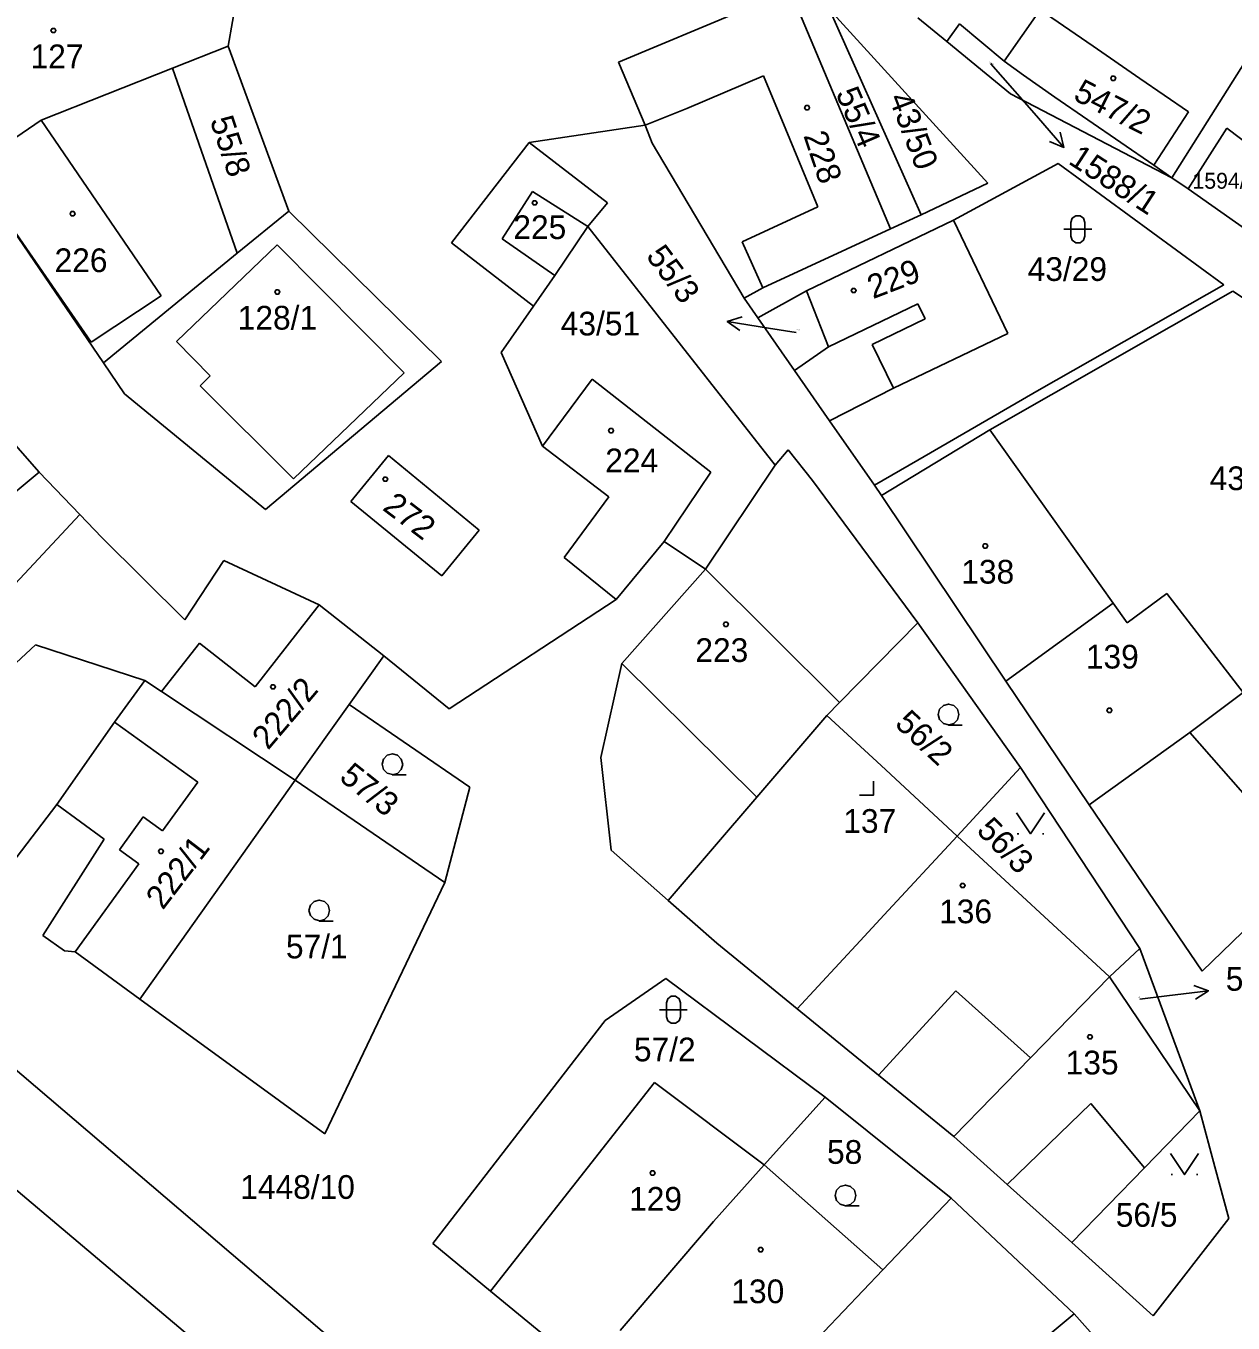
# Model space of a CAD drawing. Extents: x -580630 to -576196, y -1189024 to -1183567.
# Drawn here: x -578833.2 to -578746.6, y -1185615.1 to -1185522.1 of the extents above; entities that cross this region are included whole.
import ezdxf

# ---------------------------------------------------------------- set-up
doc = ezdxf.new("R2010")
doc.units = 0
for name, color, linetype in [('Vrstva 1', 7, 'Continuous'), ('Vrstva 16', 7, 'Continuous'), ('Vrstva 18', 7, 'Continuous'), ('Vrstva 19', 7, 'Continuous'), ('Vrstva 25', 7, 'Continuous'), ('Vrstva 4', 7, 'Continuous')]:
    doc.layers.add(name, color=color, linetype=linetype)

msp = doc.modelspace()

# ---------------------------------------------------------------- linework, layer by layer
at = {"layer": 'Vrstva 1'}
for p, q in [((-578731.57, -1185502.07), (-578751.03, -1185532.96)), ((-578818.69, -1185523.52), (-578817.05, -1185514.17)), ((-578778.1, -1185520.19), (-578771.19, -1185536.6)), ((-578790.69, -1185524.65), (-578781.89, -1185520.97)), ((-578775.57, -1185520.89), (-578769, -1185535.61)), ((-578764.22, -1185533.34), (-578775.57, -1185520.89)), ((-578767.17, -1185523.17), (-578769.25, -1185521.47)), ((-578760.47, -1185520.91), (-578763.06, -1185524.59)), ((-578760.47, -1185520.91), (-578756.67, -1185523.51)), ((-578766.25, -1185521.92), (-578767.17, -1185523.17)), ((-578766.25, -1185521.92), (-578763.06, -1185524.59)), ((-578762.6, -1185526.92), (-578767.17, -1185523.17)), ((-578822.67, -1185525.09), (-578818.69, -1185523.52)), ((-578814.34, -1185535.34), (-578818.69, -1185523.52)), ((-578756.67, -1185523.51), (-578753.33, -1185525.82)), ((-578832.1, -1185528.82), (-578822.67, -1185525.09)), ((-578822.67, -1185525.09), (-578818.03, -1185538.36)), ((-578788.8, -1185529.18), (-578790.69, -1185524.65)), ((-578763.06, -1185524.59), (-578761.66, -1185525.59)), ((-578761.66, -1185525.59), (-578759.42, -1185527.17)), ((-578753.33, -1185525.82), (-578749.83, -1185528.21)), ((-578751.03, -1185532.96), (-578762.6, -1185526.92)), ((-578759.42, -1185527.17), (-578752.33, -1185532.03)), ((-578832.1, -1185528.82), (-578837.14, -1185532.25)), ((-578749.83, -1185528.21), (-578752.33, -1185532.03)), ((-578788.8, -1185529.18), (-578797.11, -1185530.41)), ((-578788.28, -1185530.46), (-578788.8, -1185529.18)), ((-578749.86, -1185533.74), (-578747.08, -1185529.4)), ((-578747.08, -1185529.4), (-578745.22, -1185530.79)), ((-578797.11, -1185530.41), (-578802.68, -1185537.62)), ((-578791.49, -1185534.75), (-578797.11, -1185530.41)), ((-578781.69, -1185541.57), (-578788.28, -1185530.46)), ((-578827.62, -1185546.22), (-578837.14, -1185532.25)), ((-578766.69, -1185535.98), (-578759.18, -1185531.92)), ((-578747.29, -1185540.62), (-578759.18, -1185531.92)), ((-578752.33, -1185532.03), (-578751.03, -1185532.96)), ((-578769, -1185535.61), (-578764.22, -1185533.34)), ((-578751.03, -1185532.96), (-578749.86, -1185533.74)), ((-578745.82, -1185536.58), (-578749.86, -1185533.74)), ((-578818.03, -1185538.36), (-578814.34, -1185535.34)), ((-578814.34, -1185535.34), (-578803.4, -1185546.12)), ((-578792.9, -1185536.45), (-578791.49, -1185534.75)), ((-578795.26, -1185539.96), (-578792.9, -1185536.45)), ((-578779.46, -1185553.54), (-578792.9, -1185536.45)), ((-578777.23, -1185541.06), (-578766.69, -1185535.98)), ((-578769, -1185535.61), (-578771.19, -1185536.6)), ((-578766.69, -1185535.98), (-578762.79, -1185544.1)), ((-578771.19, -1185536.6), (-578780.36, -1185540.83)), ((-578827.62, -1185546.22), (-578818.03, -1185538.36)), ((-578802.68, -1185537.62), (-578796.8, -1185542.16)), ((-578796.8, -1185542.16), (-578795.26, -1185539.96)), ((-578780.36, -1185540.83), (-578781.69, -1185541.57)), ((-578780.7, -1185542.98), (-578777.23, -1185541.06)), ((-578777.23, -1185541.06), (-578775.64, -1185545.06)), ((-578764.07, -1185551.02), (-578746.66, -1185541.08)), ((-578760.55, -1185548.16), (-578747.29, -1185540.62)), ((-578746.66, -1185541.08), (-578728.09, -1185553.41)), ((-578781.69, -1185541.57), (-578780.7, -1185542.98)), ((-578799.11, -1185545.48), (-578796.8, -1185542.16)), ((-578778.07, -1185546.77), (-578780.7, -1185542.98)), ((-578841.52, -1185543.51), (-578832.24, -1185554.04)), ((-578762.79, -1185544.1), (-578770.99, -1185548.04)), ((-578796.16, -1185552.19), (-578799.11, -1185545.48)), ((-578775.64, -1185545.06), (-578778.07, -1185546.77)), ((-578826.11, -1185548.44), (-578827.62, -1185546.22)), ((-578803.4, -1185546.12), (-578816, -1185556.73)), ((-578792.58, -1185547.38), (-578796.16, -1185552.19)), ((-578792.58, -1185547.38), (-578784.08, -1185554.05)), ((-578778.07, -1185546.77), (-578775.57, -1185550.36)), ((-578816, -1185556.73), (-578826.11, -1185548.44)), ((-578770.99, -1185548.04), (-578775.57, -1185550.36)), ((-578769.25, -1185553.18), (-578760.55, -1185548.16)), ((-578772.34, -1185554.99), (-578775.57, -1185550.36)), ((-578764.07, -1185551.02), (-578771.85, -1185555.72)), ((-578755.23, -1185563.44), (-578764.07, -1185551.02)), ((-578796.16, -1185552.19), (-578791.39, -1185555.83)), ((-578807.2, -1185552.86), (-578809.89, -1185556.16)), ((-578800.68, -1185558.21), (-578807.2, -1185552.86)), ((-578778.53, -1185552.44), (-578779.46, -1185553.54)), ((-578776.79, -1185554.66), (-578778.53, -1185552.44)), ((-578772.34, -1185554.99), (-578769.25, -1185553.18)), ((-578832.24, -1185554.04), (-578855.96, -1185573.95)), ((-578832.24, -1185554.04), (-578829.33, -1185557.09)), ((-578786.58, -1185557.78), (-578784.08, -1185554.05)), ((-578784.47, -1185561.01), (-578779.46, -1185553.54)), ((-578769.23, -1185564.85), (-578776.79, -1185554.66)), ((-578772.34, -1185554.99), (-578771.85, -1185555.72)), ((-578791.39, -1185555.83), (-578794.59, -1185560.17)), ((-578771.85, -1185555.72), (-578762.92, -1185569.03)), ((-578809.89, -1185556.16), (-578803.36, -1185561.49)), ((-578850.68, -1185579.93), (-578829.33, -1185557.09)), ((-578829.33, -1185557.09), (-578827.73, -1185558.74)), ((-578787.42, -1185559.03), (-578786.58, -1185557.78)), ((-578827.73, -1185558.74), (-578821.8, -1185564.64)), ((-578803.36, -1185561.49), (-578800.68, -1185558.21)), ((-578790.86, -1185563.19), (-578787.42, -1185559.03)), ((-578787.42, -1185559.03), (-578784.47, -1185561.01)), ((-578821.8, -1185564.64), (-578818.99, -1185560.38)), ((-578812.16, -1185563.57), (-578818.99, -1185560.38)), ((-578794.59, -1185560.17), (-578790.86, -1185563.19)), ((-578790.45, -1185567.77), (-578784.47, -1185561.01)), ((-578790.86, -1185563.19), (-578802.84, -1185571.01)), ((-578762.92, -1185569.03), (-578755.23, -1185563.44)), ((-578754.22, -1185564.85), (-578755.23, -1185563.44)), ((-578751.39, -1185562.75), (-578754.22, -1185564.85)), ((-578745.91, -1185569.85), (-578751.39, -1185562.75)), ((-578807.52, -1185567.22), (-578812.16, -1185563.57)), ((-578774.86, -1185570.57), (-578769.23, -1185564.85)), ((-578769.23, -1185564.85), (-578761.89, -1185575.22)), ((-578849.08, -1185581.71), (-578832.49, -1185566.44)), ((-578832.49, -1185566.44), (-578824.66, -1185568.98)), ((-578807.52, -1185567.22), (-578810.02, -1185570.72)), ((-578802.84, -1185571.01), (-578807.52, -1185567.22)), ((-578791.96, -1185574.52), (-578790.45, -1185567.77)), ((-578824.66, -1185568.98), (-578826.83, -1185571.98)), ((-578824.66, -1185568.98), (-578823.46, -1185569.78)), ((-578762.92, -1185569.03), (-578756.96, -1185577.9)), ((-578823.46, -1185569.78), (-578813.89, -1185576.14)), ((-578749.73, -1185572.71), (-578745.91, -1185569.85)), ((-578810.02, -1185570.72), (-578813.89, -1185576.14)), ((-578810.02, -1185570.72), (-578801.35, -1185576.64)), ((-578775.77, -1185571.5), (-578774.86, -1185570.57)), ((-578775.77, -1185571.5), (-578780.78, -1185577.34)), ((-578771.88, -1185575.09), (-578775.77, -1185571.5)), ((-578826.83, -1185571.98), (-578830.97, -1185577.88)), ((-578749.73, -1185572.71), (-578756.96, -1185577.9)), ((-578791.22, -1185581.15), (-578791.96, -1185574.52)), ((-578766.42, -1185580.14), (-578771.88, -1185575.09)), ((-578766.42, -1185580.14), (-578761.89, -1185575.22)), ((-578753.33, -1185588.21), (-578761.89, -1185575.22)), ((-578813.89, -1185576.14), (-578825.02, -1185591.83)), ((-578813.89, -1185576.14), (-578803.15, -1185583.47)), ((-578803.15, -1185583.47), (-578801.35, -1185576.64)), ((-578780.78, -1185577.34), (-578787.15, -1185584.75)), ((-578830.97, -1185577.88), (-578840.93, -1185590.91)), ((-578827.57, -1185580.37), (-578830.97, -1185577.88)), ((-578756.96, -1185577.9), (-578748.86, -1185589.83)), ((-578771.65, -1185585.79), (-578766.42, -1185580.14)), ((-578755.49, -1185590.23), (-578766.42, -1185580.14)), ((-578831.96, -1185587.27), (-578827.57, -1185580.37)), ((-578787.15, -1185584.75), (-578791.22, -1185581.15)), ((-578740.35, -1185581.57), (-578748.86, -1185589.83)), ((-578811.76, -1185601.48), (-578803.15, -1185583.47)), ((-578783.66, -1185587.83), (-578787.15, -1185584.75)), ((-578773.38, -1185587.66), (-578771.65, -1185585.79)), ((-578830.41, -1185588.36), (-578831.96, -1185587.27)), ((-578777.9, -1185592.53), (-578773.38, -1185587.66)), ((-578829.66, -1185588.44), (-578830.41, -1185588.36)), ((-578825.02, -1185591.83), (-578829.66, -1185588.44)), ((-578779.74, -1185591.03), (-578783.66, -1185587.83)), ((-578755.49, -1185590.23), (-578753.33, -1185588.21)), ((-578749.02, -1185599.84), (-578753.33, -1185588.21)), ((-578787.3, -1185590.36), (-578791.66, -1185593.37)), ((-578775.89, -1185598.87), (-578787.3, -1185590.36)), ((-578761.17, -1185596.05), (-578755.49, -1185590.23)), ((-578749.02, -1185599.84), (-578755.49, -1185590.23)), ((-578764.45, -1185656.14), (-578840.93, -1185590.91)), ((-578777.9, -1185592.53), (-578779.74, -1185591.03)), ((-578825.02, -1185591.83), (-578811.76, -1185601.48)), ((-578772.07, -1185597.28), (-578777.9, -1185592.53)), ((-578791.66, -1185593.37), (-578804.02, -1185609.36)), ((-578766.66, -1185601.69), (-578761.17, -1185596.05)), ((-578788.12, -1185597.8), (-578799.88, -1185612.76)), ((-578780.25, -1185603.72), (-578788.12, -1185597.8)), ((-578766.66, -1185601.69), (-578772.07, -1185597.28)), ((-578842.76, -1185598.03), (-578767.43, -1185661.53)), ((-578780.25, -1185603.72), (-578775.89, -1185598.87)), ((-578766.85, -1185606.09), (-578775.89, -1185598.87)), ((-578749.02, -1185599.84), (-578752.98, -1185603.92)), ((-578747.94, -1185603.85), (-578749.02, -1185599.84)), ((-578766.66, -1185601.69), (-578762.83, -1185605.12)), ((-578783.88, -1185607.77), (-578780.25, -1185603.72)), ((-578780.25, -1185603.72), (-578771.76, -1185611.24)), ((-578752.98, -1185603.92), (-578758.19, -1185609.29)), ((-578746.94, -1185607.55), (-578747.94, -1185603.85)), ((-578762.83, -1185605.12), (-578758.19, -1185609.29)), ((-578771.76, -1185611.24), (-578766.85, -1185606.09)), ((-578758.03, -1185614.39), (-578766.85, -1185606.09)), ((-578783.88, -1185607.77), (-578790.59, -1185615.58)), ((-578752.36, -1185614.53), (-578746.94, -1185607.55)), ((-578804.02, -1185609.36), (-578799.88, -1185612.76)), ((-578758.19, -1185609.29), (-578752.36, -1185614.53)), ((-578780.45, -1185620.36), (-578771.76, -1185611.24)), ((-578799.88, -1185612.76), (-578793.01, -1185618.4)), ((-578762.65, -1185618.22), (-578758.03, -1185614.39)), ((-578758.03, -1185614.39), (-578755.17, -1185617.6))]:
    msp.add_line(p, q, dxfattribs=at)
at = {"layer": 'Vrstva 16'}
for p, q in [((-578764.01, -1185524.78), (-578760.74, -1185528.51)), ((-578758.763, -1185530.767), (-578760.74, -1185528.51)), ((-578782.901, -1185543.24), (-578779.94, -1185543.72)), ((-578777.97, -1185544.04), (-578779.94, -1185543.72)), ((-578748.402, -1185591.229), (-578751.38, -1185591.59)), ((-578753.33, -1185591.83), (-578751.38, -1185591.59))]:
    msp.add_line(p, q, dxfattribs=at)
for points in [[(-578759.046, -1185529.685), (-578758.763, -1185530.767), (-578759.798, -1185530.344)], [(-578781.994, -1185543.893), (-578782.901, -1185543.24), (-578781.834, -1185542.906)], [(-578749.455, -1185590.853), (-578748.402, -1185591.229), (-578749.334, -1185591.846)]]:
    msp.add_lwpolyline(points, dxfattribs=at)
at = {"layer": 'Vrstva 25'}
for p, q in [((-578762.11, -1185579.98), (-578762.01, -1185579.98)), ((-578760.31, -1185579.98), (-578760.21, -1185579.98)), ((-578751.07, -1185604.41), (-578750.97, -1185604.41)), ((-578749.27, -1185604.41), (-578749.17, -1185604.41))]:
    msp.add_line(p, q, dxfattribs=at)
for points in [[(-578831.12, -1185522.24), (-578831.03, -1185522.39), (-578831.12, -1185522.54), (-578831.3, -1185522.54), (-578831.39, -1185522.39), (-578831.3, -1185522.24)], [(-578755.14, -1185525.66), (-578755.05, -1185525.81), (-578755.14, -1185525.96), (-578755.32, -1185525.96), (-578755.41, -1185525.81), (-578755.32, -1185525.66)], [(-578777.09, -1185527.77), (-578777, -1185527.92), (-578777.09, -1185528.07), (-578777.27, -1185528.07), (-578777.36, -1185527.92), (-578777.27, -1185527.77)], [(-578796.62, -1185534.59), (-578796.53, -1185534.74), (-578796.62, -1185534.89), (-578796.8, -1185534.89), (-578796.89, -1185534.74), (-578796.8, -1185534.59)], [(-578829.75, -1185535.37), (-578829.66, -1185535.52), (-578829.75, -1185535.67), (-578829.93, -1185535.67), (-578830.02, -1185535.52), (-578829.93, -1185535.37)], [(-578758.27, -1185536.14), (-578758.17, -1185535.85), (-578757.92, -1185535.67), (-578757.61, -1185535.67), (-578757.36, -1185535.85), (-578757.26, -1185536.14), (-578757.26, -1185537.14), (-578757.36, -1185537.43), (-578757.61, -1185537.61), (-578757.92, -1185537.61), (-578758.17, -1185537.43), (-578758.27, -1185537.14)], [(-578815.07, -1185540.98), (-578814.98, -1185541.13), (-578815.07, -1185541.28), (-578815.25, -1185541.28), (-578815.34, -1185541.13), (-578815.25, -1185540.98)], [(-578773.75, -1185540.88), (-578773.66, -1185541.03), (-578773.75, -1185541.18), (-578773.93, -1185541.18), (-578774.02, -1185541.03), (-578773.93, -1185540.88)], [(-578791.14, -1185550.92), (-578791.05, -1185551.07), (-578791.14, -1185551.22), (-578791.32, -1185551.22), (-578791.41, -1185551.07), (-578791.32, -1185550.92)], [(-578807.33, -1185554.4), (-578807.24, -1185554.55), (-578807.33, -1185554.7), (-578807.51, -1185554.7), (-578807.6, -1185554.55), (-578807.51, -1185554.4)], [(-578764.32, -1185559.19), (-578764.23, -1185559.34), (-578764.32, -1185559.49), (-578764.5, -1185559.49), (-578764.59, -1185559.34), (-578764.5, -1185559.19)], [(-578782.91, -1185564.81), (-578782.82, -1185564.96), (-578782.91, -1185565.11), (-578783.09, -1185565.11), (-578783.18, -1185564.96), (-578783.09, -1185564.81)], [(-578815.38, -1185569.29), (-578815.29, -1185569.44), (-578815.38, -1185569.59), (-578815.56, -1185569.59), (-578815.65, -1185569.44), (-578815.56, -1185569.29)], [(-578755.41, -1185570.98), (-578755.32, -1185571.13), (-578755.41, -1185571.28), (-578755.59, -1185571.28), (-578755.68, -1185571.13), (-578755.59, -1185570.98)], [(-578823.41, -1185581.08), (-578823.32, -1185581.23), (-578823.41, -1185581.38), (-578823.59, -1185581.38), (-578823.68, -1185581.23), (-578823.59, -1185581.08)], [(-578765.93, -1185583.54), (-578765.84, -1185583.69), (-578765.93, -1185583.84), (-578766.11, -1185583.84), (-578766.2, -1185583.69), (-578766.11, -1185583.54)], [(-578787.27, -1185592.09), (-578787.17, -1185591.8), (-578786.92, -1185591.62), (-578786.61, -1185591.62), (-578786.36, -1185591.8), (-578786.26, -1185592.09), (-578786.26, -1185593.09), (-578786.36, -1185593.38), (-578786.61, -1185593.56), (-578786.92, -1185593.56), (-578787.17, -1185593.38), (-578787.27, -1185593.09)], [(-578756.81, -1185594.38), (-578756.72, -1185594.53), (-578756.81, -1185594.68), (-578756.99, -1185594.68), (-578757.08, -1185594.53), (-578756.99, -1185594.38)], [(-578788.17, -1185604.15), (-578788.08, -1185604.3), (-578788.17, -1185604.45), (-578788.35, -1185604.45), (-578788.44, -1185604.3), (-578788.35, -1185604.15)], [(-578780.42, -1185609.64), (-578780.33, -1185609.79), (-578780.42, -1185609.94), (-578780.6, -1185609.94), (-578780.69, -1185609.79), (-578780.6, -1185609.64)]]:
    msp.add_lwpolyline(points, close=True, dxfattribs=at)
for points in [[(-578758.77, -1185536.64), (-578757.5, -1185536.64), (-578756.77, -1185536.64)], [(-578767.03, -1185572.16), (-578767.41, -1185572.06), (-578767.68, -1185571.79), (-578767.78, -1185571.42), (-578767.68, -1185571.05), (-578767.41, -1185570.78), (-578767.04, -1185570.68), (-578766.67, -1185570.78), (-578766.4, -1185571.05), (-578766.3, -1185571.43), (-578766.4, -1185571.81), (-578766.67, -1185572.08), (-578767.05, -1185572.18), (-578766.05, -1185572.18)], [(-578806.9, -1185575.73), (-578807.28, -1185575.63), (-578807.55, -1185575.36), (-578807.65, -1185574.99), (-578807.55, -1185574.62), (-578807.28, -1185574.35), (-578806.91, -1185574.25), (-578806.54, -1185574.35), (-578806.27, -1185574.62), (-578806.17, -1185575), (-578806.27, -1185575.38), (-578806.54, -1185575.65), (-578806.92, -1185575.75), (-578805.92, -1185575.75)], [(-578773.43, -1185577.21), (-578772.43, -1185577.21), (-578772.43, -1185576.21)], [(-578762.16, -1185578.48), (-578761.16, -1185579.98), (-578760.16, -1185578.48)], [(-578812.14, -1185586.21), (-578812.52, -1185586.11), (-578812.79, -1185585.84), (-578812.89, -1185585.47), (-578812.79, -1185585.1), (-578812.52, -1185584.83), (-578812.15, -1185584.73), (-578811.78, -1185584.83), (-578811.51, -1185585.1), (-578811.41, -1185585.48), (-578811.51, -1185585.86), (-578811.78, -1185586.13), (-578812.16, -1185586.23), (-578811.16, -1185586.23)], [(-578787.77, -1185592.59), (-578786.5, -1185592.59), (-578785.77, -1185592.59)], [(-578751.12, -1185602.91), (-578750.12, -1185604.41), (-578749.12, -1185602.91)], [(-578774.42, -1185606.64), (-578774.8, -1185606.54), (-578775.07, -1185606.27), (-578775.17, -1185605.9), (-578775.07, -1185605.53), (-578774.8, -1185605.26), (-578774.43, -1185605.16), (-578774.06, -1185605.26), (-578773.79, -1185605.53), (-578773.69, -1185605.91), (-578773.79, -1185606.29), (-578774.06, -1185606.56), (-578774.44, -1185606.66), (-578773.44, -1185606.66)]]:
    msp.add_lwpolyline(points, dxfattribs=at)
at = {"layer": 'Vrstva 4'}
for p, q in [((-578785.81, -1185527.99), (-578780.3, -1185525.63)), ((-578780.3, -1185525.63), (-578778.71, -1185529.48)), ((-578788.8, -1185529.18), (-578785.81, -1185527.99)), ((-578823.49, -1185541.42), (-578832.1, -1185528.82)), ((-578778.71, -1185529.48), (-578776.41, -1185535.04)), ((-578828.5, -1185544.73), (-578837.14, -1185532.25)), ((-578799.04, -1185537.33), (-578796.86, -1185533.94)), ((-578796.86, -1185533.94), (-578792.9, -1185536.45)), ((-578776.41, -1185535.04), (-578781.84, -1185537.53)), ((-578795.26, -1185539.96), (-578799.04, -1185537.33)), ((-578815.18, -1185537.76), (-578822.39, -1185544.68)), ((-578806.07, -1185546.92), (-578815.18, -1185537.76)), ((-578781.84, -1185537.53), (-578780.36, -1185540.83)), ((-578828.5, -1185544.73), (-578823.49, -1185541.42)), ((-578769.24, -1185541.98), (-578775.64, -1185545.06)), ((-578768.72, -1185543.07), (-578769.24, -1185541.98)), ((-578772.51, -1185544.89), (-578768.72, -1185543.07)), ((-578822.39, -1185544.68), (-578819.98, -1185547.15)), ((-578770.99, -1185548.04), (-578772.51, -1185544.89)), ((-578819.98, -1185547.15), (-578820.7, -1185547.85)), ((-578814, -1185554.54), (-578806.07, -1185546.92)), ((-578820.7, -1185547.85), (-578814, -1185554.54)), ((-578784.47, -1185561.01), (-578774.86, -1185570.57)), ((-578812.16, -1185563.57), (-578816.76, -1185569.43)), ((-578820.73, -1185566.31), (-578823.46, -1185569.78)), ((-578816.76, -1185569.43), (-578820.73, -1185566.31)), ((-578790.45, -1185567.77), (-578780.78, -1185577.34)), ((-578820.87, -1185576.28), (-578826.83, -1185571.98)), ((-578744.55, -1185578.61), (-578749.73, -1185572.71)), ((-578823.39, -1185579.77), (-578820.87, -1185576.28)), ((-578826.47, -1185581.12), (-578824.77, -1185578.77)), ((-578824.77, -1185578.77), (-578823.39, -1185579.77)), ((-578825.09, -1185582.12), (-578826.47, -1185581.12)), ((-578829.66, -1185588.44), (-578825.09, -1185582.12)), ((-578772.07, -1185597.28), (-578766.51, -1185591.24)), ((-578766.51, -1185591.24), (-578761.17, -1185596.05)), ((-578762.83, -1185605.12), (-578756.83, -1185599.32)), ((-578756.83, -1185599.32), (-578752.98, -1185603.92))]:
    msp.add_line(p, q, dxfattribs=at)

# ---------------------------------------------------------------- texts
at = {"layer": 'Vrstva 16'}
for s, rotation, p in [('1588/1', 326.98701, (-578758.527, -1185531.889)), ('55/3', 306.93349, (-578788.778, -1185538.574))]:
    msp.add_text(s, height=1.7, rotation=rotation, dxfattribs=at).set_placement(p)
msp.add_text('56/4', height=1.7, dxfattribs=at).set_placement((-578747.163, -1185591.23))
at = {"layer": 'Vrstva 18'}
for s, height, rotation, p in [('1588/1', 0.1, 323.77845, (-578764.177, -1185524.657)), ('55/4', 1.7, 293.29709, (-578775.152, -1185526.884)), ('43/50', 1.7, 291.00526, (-578771.348, -1185527.215)), ('55/8', 1.7, 288.31236, (-578820.008, -1185528.827)), ('56/2', 1.7, 316.96025, (-578770.964, -1185572.185)), ('57/3', 1.7, 321.42932, (-578810.799, -1185576.071)), ('56/3', 1.7, 314.43924, (-578765.105, -1185579.815)), ('56/4', 0.1, 313.5798, (-578753.443, -1185591.711))]:
    msp.add_text(s, height=height, rotation=rotation, dxfattribs=at).set_placement(p)
for s, height, p in [('1594/12', 1.14, (-578749.551, -1185533.73)), ('43/29', 1.7, (-578761.364, -1185540.34)), ('43/51', 1.7, (-578794.839, -1185544.25)), ('55/3', 0.1, (-578777.942, -1185543.94)), ('43/28', 1.7, (-578748.314, -1185555.34)), ('57/1', 1.7, (-578814.543, -1185588.91)), ('57/2', 1.7, (-578789.594, -1185596.29)), ('58', 1.7, (-578775.752, -1185603.64)), ('1448/10', 1.7, (-578817.819, -1185606.15)), ('56/5', 1.7, (-578755.048, -1185608.15))]:
    msp.add_text(s, height=height, dxfattribs=at).set_placement(p)
at = {"layer": 'Vrstva 19'}
for s, p in [('127', (-578832.85, -1185525.09)), ('225', (-578798.238, -1185537.34)), ('226', (-578831.131, -1185539.71)), ('128/1', (-578817.998, -1185543.83)), ('224', (-578791.651, -1185554.06)), ('138', (-578766.123, -1185562.04)), ('223', (-578785.189, -1185567.66)), ('139', (-578757.193, -1185568.13)), ('137', (-578774.583, -1185579.91)), ('136', (-578767.713, -1185586.39)), ('135', (-578758.64, -1185597.23)), ('129', (-578789.94, -1185607)), ('130', (-578782.61, -1185613.63))]:
    msp.add_text(s, height=1.7, dxfattribs=at).set_placement(p)
for s, rotation, p in [('547/2', 332.94578, (-578758.179, -1185527.312)), ('228', 288.65614, (-578777.459, -1185529.92)), ('229', 21.02755, (-578772.452, -1185541.654)), ('272', 322.74713, (-578807.691, -1185556.712)), ('222/2', 49.67544, (-578815.822, -1185574.032)), ('222/1', 52.54023, (-578823.371, -1185585.494))]:
    msp.add_text(s, height=1.7, rotation=rotation, dxfattribs=at).set_placement(p)

doc.saveas('drawing.dxf')
